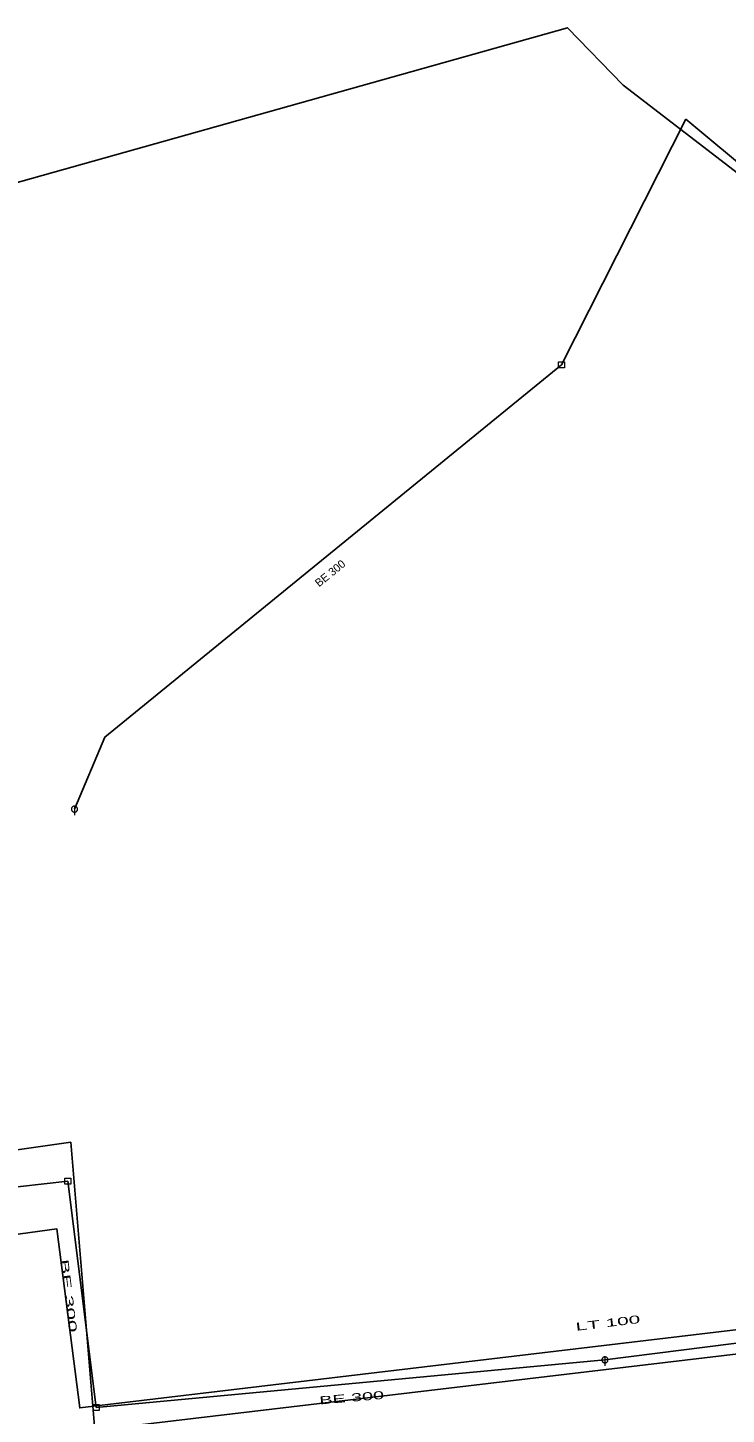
# Model space of a CAD drawing. Extents: x -687515 to -686506, y -974029 to -973461.
# Drawn here: x -686958.8 to -686900.6, y -973577 to -973461.4 of the extents above; entities that cross this region are included whole.
import ezdxf
from ezdxf.enums import TextEntityAlignment as Align

# ---------------------------------------------------------------- set-up
doc = ezdxf.new("R2010")
doc.units = 0
doc.header["$LTSCALE"] = 0.27
for name, color, linetype, lineweight in [('1', 7, 'Continuous', 13), ('14', 7, 'Continuous', 25), ('17', 7, 'Continuous', 25), ('22', 7, 'Continuous', 13)]:
    doc.layers.add(name, color=color, linetype=linetype, lineweight=lineweight)

msp = doc.modelspace()

# ---------------------------------------------------------------- linework, layer by layer
at = {"layer": '14'}
for p, q in [((-686914.292, -973489.532), (-686903.939, -973469.054)), ((-686886.339, -973483.774), (-686903.939, -973469.054)), ((-686955.417, -973557.554), (-686991.728, -973561.661)), ((-686953.069, -973576.425), (-686955.417, -973557.554)), ((-686861.107, -973566.122), (-686910.675, -973572.458)), ((-686910.676, -973572.458), (-686953.069, -973576.425))]:
    msp.add_line(p, q, dxfattribs=at)
msp.add_lwpolyline([(-686954.868, -973526.559), (-686952.334, -973520.553), (-686914.292, -973489.532)], dxfattribs=at)
at = {"layer": '17'}
for points in [[(-686909.161, -973466.235), (-686913.807, -973461.442), (-687024.592, -973492.592), (-687041.911, -973493.995), (-687051.861, -973493.177), (-687062.728, -973488.354), (-687072.464, -973486.138), (-687076.669, -973485.884), (-687084.129, -973486.42), (-687105.732, -973490.966), (-687125.756, -973492.743)], [(-686645.309, -973464.46), (-686646.34, -973464.75), (-686680.188, -973471.317), (-686771.188, -973470.317), (-686761.188, -973557.317), (-686894.188, -973571.317), (-686953.188, -973578.317), (-686955.188, -973554.317), (-687116.188, -973577.317), (-687229.188, -973601.317), (-687468.188, -973649.317), (-687458.188, -973700.317)], [(-686843.189, -973481.177), (-686852.556, -973484.484), (-686863.574, -973493.486), (-686869.489, -973503.408), (-686871.583, -973503.866), (-686878.192, -973492.227), (-686888.848, -973481.844), (-686909.161, -973466.235)], [(-686980.567, -973564.875), (-686956.331, -973561.544), (-686954.436, -973576.46), (-686865.945, -973565.93)]]:
    msp.add_lwpolyline(points, dxfattribs=at)
at = {"layer": '22'}
for p, q in [((-686954.867, -973526.307), (-686954.868, -973527.051)), ((-686910.674, -973572.206), (-686910.675, -973572.95))]:
    msp.add_line(p, q, dxfattribs=at)
for points in [[(-686914.54, -973489.284), (-686914.044, -973489.284), (-686914.044, -973489.78), (-686914.54, -973489.78)], [(-686954.616, -973526.559), (-686954.617, -973526.533), (-686954.621, -973526.507), (-686954.627, -973526.481), (-686954.637, -973526.457), (-686954.649, -973526.433), (-686954.663, -973526.411), (-686954.68, -973526.39), (-686954.698, -973526.372), (-686954.719, -973526.355), (-686954.741, -973526.341), (-686954.765, -973526.329), (-686954.789, -973526.319), (-686954.815, -973526.313), (-686954.841, -973526.309), (-686954.867, -973526.307), (-686954.893, -973526.308), (-686954.919, -973526.312), (-686954.945, -973526.318), (-686954.97, -973526.328), (-686954.993, -973526.34), (-686955.015, -973526.354), (-686955.036, -973526.371), (-686955.054, -973526.389), (-686955.071, -973526.41), (-686955.085, -973526.432), (-686955.097, -973526.456), (-686955.107, -973526.48), (-686955.114, -973526.506), (-686955.118, -973526.532), (-686955.12, -973526.558), (-686955.119, -973526.584), (-686955.115, -973526.61), (-686955.108, -973526.636), (-686955.098, -973526.661), (-686955.086, -973526.684), (-686955.072, -973526.706), (-686955.055, -973526.727), (-686955.037, -973526.745), (-686955.016, -973526.762), (-686954.994, -973526.776), (-686954.971, -973526.788), (-686954.946, -973526.798), (-686954.92, -973526.805), (-686954.894, -973526.809), (-686954.868, -973526.811), (-686954.842, -973526.81), (-686954.816, -973526.806), (-686954.79, -973526.799), (-686954.766, -973526.789), (-686954.742, -973526.777), (-686954.72, -973526.763), (-686954.699, -973526.746), (-686954.681, -973526.728), (-686954.664, -973526.707), (-686954.65, -973526.685), (-686954.638, -973526.662), (-686954.628, -973526.637), (-686954.622, -973526.611), (-686954.618, -973526.585)], [(-686955.665, -973557.306), (-686955.169, -973557.306), (-686955.169, -973557.802), (-686955.665, -973557.802)], [(-686910.423, -973572.458), (-686910.424, -973572.432), (-686910.428, -973572.406), (-686910.434, -973572.38), (-686910.444, -973572.356), (-686910.456, -973572.332), (-686910.47, -973572.31), (-686910.487, -973572.289), (-686910.505, -973572.271), (-686910.526, -973572.254), (-686910.548, -973572.24), (-686910.572, -973572.228), (-686910.596, -973572.218), (-686910.622, -973572.212), (-686910.648, -973572.208), (-686910.674, -973572.206), (-686910.7, -973572.207), (-686910.726, -973572.211), (-686910.752, -973572.217), (-686910.777, -973572.227), (-686910.8, -973572.239), (-686910.822, -973572.253), (-686910.843, -973572.27), (-686910.861, -973572.288), (-686910.878, -973572.309), (-686910.892, -973572.331), (-686910.904, -973572.355), (-686910.914, -973572.379), (-686910.921, -973572.405), (-686910.925, -973572.431), (-686910.927, -973572.457), (-686910.926, -973572.483), (-686910.922, -973572.509), (-686910.915, -973572.535), (-686910.905, -973572.56), (-686910.893, -973572.583), (-686910.879, -973572.605), (-686910.862, -973572.626), (-686910.844, -973572.644), (-686910.823, -973572.661), (-686910.801, -973572.675), (-686910.778, -973572.687), (-686910.753, -973572.697), (-686910.727, -973572.704), (-686910.701, -973572.708), (-686910.675, -973572.71), (-686910.649, -973572.709), (-686910.623, -973572.705), (-686910.597, -973572.698), (-686910.573, -973572.688), (-686910.549, -973572.676), (-686910.527, -973572.662), (-686910.506, -973572.645), (-686910.488, -973572.627), (-686910.471, -973572.606), (-686910.457, -973572.584), (-686910.445, -973572.561), (-686910.435, -973572.536), (-686910.429, -973572.51), (-686910.425, -973572.484)], [(-686953.317, -973576.177), (-686952.821, -973576.177), (-686952.821, -973576.673), (-686953.317, -973576.673)]]:
    msp.add_lwpolyline(points, close=True, dxfattribs=at)

# ---------------------------------------------------------------- texts
at = {"layer": '1'}
msp.add_text('BE 300', height=0.6667, rotation=39, dxfattribs=at).set_placement((-686933.361, -973507.164), align=Align.CENTER)
for s, rotation, width, p in [('BE 300', 277, 2.1, (-686955.679, -973567.155)), ('LT 100', 7, 1.95, (-686910.387, -973569.707)), ('BE 300', 5, 1.85, (-686931.751, -973575.935))]:
    msp.add_text(s, height=0.6667, rotation=rotation, dxfattribs=dict(at, width=width)).set_placement(p, align=Align.CENTER)

doc.saveas('drawing.dxf')
